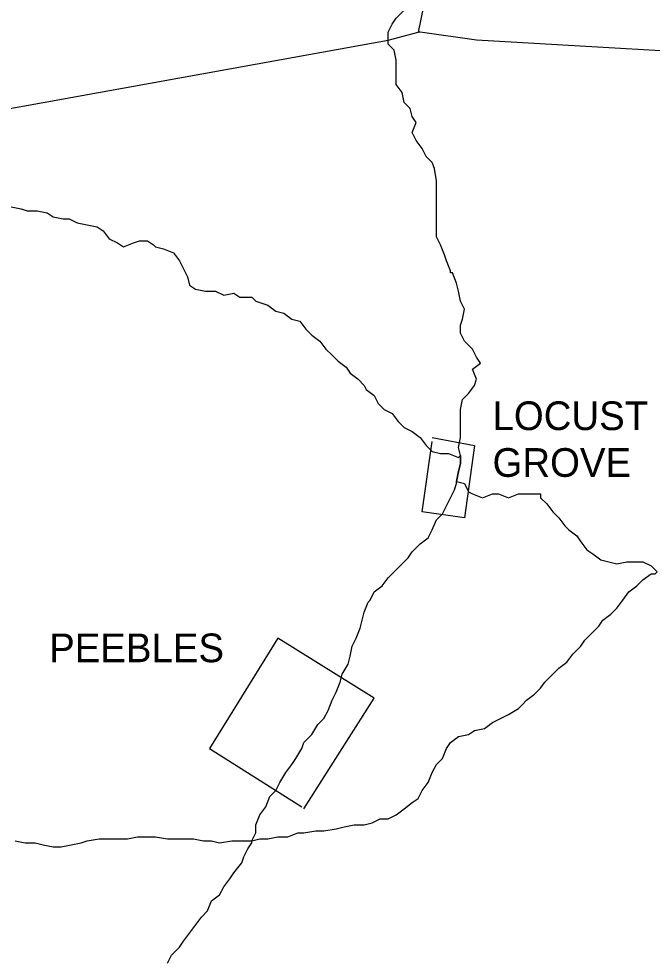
# Model space of a CAD drawing. Extents: x 0 to 34, y 0 to 22.
# Drawn here: x 4.42 to 4.851, y 17.302 to 17.942 of the extents above; entities that cross this region are included whole.
import ezdxf

# ---------------------------------------------------------------- set-up
doc = ezdxf.new("R2010")
doc.units = 0
doc.layers.add('Default', color=7, linetype='Continuous')

msp = doc.modelspace()

# ---------------------------------------------------------------- linework, layer by layer
at = {"layer": 'Default'}
for points in [[(4.8119, 18.57523), (4.78736, 18.44297), (4.76691, 18.32572), (4.75327, 18.24664), (4.73828, 18.1662), (4.72191, 18.0803), (4.69192, 17.93305)], [(4.67147, 17.9276), (4.67147, 17.93305), (4.67419, 17.93851), (4.67692, 17.9426), (4.68238, 17.94805), (4.68647, 17.95351), (4.69192, 17.9576), (4.69192, 17.96305), (4.68919, 17.9685), (4.69192, 17.97396), (4.68783, 17.97941), (4.68783, 17.98623), (4.69056, 17.99168), (4.69192, 17.9985), (4.69192, 18.00668), (4.69192, 18.01077), (4.69192, 18.01077)], [(3.67617, 17.78581), (3.72662, 17.78308), (3.89159, 17.77762), (3.98294, 17.79671), (4.2938, 17.85943), (4.67147, 17.9276), (4.69192, 17.93305)], [(4.94279, 17.91533), (4.73146, 17.9276), (4.69328, 17.93305), (4.69192, 17.93305)], [(4.71373, 17.77081), (4.71101, 17.77762), (4.70964, 17.78171), (4.70692, 17.78853), (4.70419, 17.79399), (4.70419, 17.8008), (4.70419, 17.80762), (4.70419, 17.81444), (4.70419, 17.81989), (4.70419, 17.82671), (4.70419, 17.83216), (4.70283, 17.84034), (4.70146, 17.84443), (4.69737, 17.84852), (4.69465, 17.85398), (4.69056, 17.85943), (4.68783, 17.86488), (4.69056, 17.8717), (4.68783, 17.87579), (4.68647, 17.88124), (4.68238, 17.88533), (4.68101, 17.89215), (4.67692, 17.89761), (4.67692, 17.9017), (4.67692, 17.90851), (4.67692, 17.91397), (4.67556, 17.92078), (4.67147, 17.92487), (4.67147, 17.92624), (4.67147, 17.9276)], [(4.36743, 17.82262), (4.37152, 17.81853), (4.37833, 17.8158), (4.38515, 17.81716), (4.3906, 17.81853), (4.39606, 17.81716), (4.40151, 17.8158), (4.40833, 17.81171), (4.41514, 17.81444), (4.42196, 17.81307), (4.42605, 17.81171), (4.43287, 17.81171), (4.43969, 17.81035), (4.44378, 17.80762), (4.45059, 17.80626), (4.45468, 17.80626)], [(4.45468, 17.80626), (4.46014, 17.80353), (4.46695, 17.80217), (4.47377, 17.8008), (4.47786, 17.79808), (4.48195, 17.79262), (4.48741, 17.7899), (4.4915, 17.78717), (4.49831, 17.7899), (4.5024, 17.79126), (4.50786, 17.79126), (4.51195, 17.78853), (4.51331, 17.78717)], [(4.51331, 17.78717), (4.51876, 17.78581), (4.52558, 17.78308), (4.52967, 17.77762), (4.5324, 17.77217), (4.53513, 17.76672), (4.53649, 17.76126), (4.54058, 17.75854), (4.5474, 17.75717), (4.55421, 17.75717), (4.55967, 17.75445), (4.56648, 17.75581), (4.57057, 17.75308), (4.57194, 17.75308), (4.57194, 17.75308)], [(4.72055, 17.64537), (4.71919, 17.65083), (4.72055, 17.65764), (4.72055, 17.6631), (4.72055, 17.67128), (4.72055, 17.67673), (4.72191, 17.68355), (4.726, 17.68764), (4.7301, 17.69309), (4.73146, 17.69718), (4.72873, 17.704), (4.73419, 17.70809), (4.73146, 17.71218), (4.72873, 17.71763), (4.72328, 17.72309), (4.72055, 17.72854), (4.72055, 17.734), (4.72191, 17.73809), (4.72328, 17.7449), (4.72055, 17.75036), (4.71919, 17.75717), (4.71782, 17.76263), (4.7151, 17.76944), (4.71373, 17.76944), (4.71373, 17.77081)], [(4.57194, 17.75308), (4.57876, 17.75308), (4.58148, 17.75036), (4.58966, 17.74763), (4.59512, 17.74354), (4.60057, 17.74218), (4.60602, 17.73809), (4.61148, 17.73672), (4.61557, 17.73127), (4.61966, 17.72718), (4.62511, 17.72309), (4.6292, 17.71763), (4.63329, 17.71354), (4.63738, 17.70945), (4.64284, 17.70536), (4.64556, 17.70127), (4.65102, 17.69718), (4.65511, 17.69309), (4.65511, 17.69309), (4.65647, 17.69037)], [(4.65647, 17.69037), (4.66192, 17.68628), (4.66465, 17.68082), (4.66874, 17.67673), (4.67419, 17.674), (4.67829, 17.66855), (4.68238, 17.66446), (4.68783, 17.66173), (4.69328, 17.65764), (4.69737, 17.65219), (4.70146, 17.6481), (4.70692, 17.64674), (4.71237, 17.64674), (4.71919, 17.64401), (4.72055, 17.64537)], [(4.70146, 17.65764), (4.7301, 17.65219), (4.72328, 17.60311), (4.69465, 17.6072), (4.70146, 17.65492)], [(4.72055, 17.64537), (4.72055, 17.63992), (4.71919, 17.63447), (4.71782, 17.62765)], [(4.71782, 17.62765), (4.71919, 17.63447), (4.72055, 17.63992), (4.72055, 17.64537)], [(4.6592, 17.54721), (4.66192, 17.55266), (4.66738, 17.55675), (4.67147, 17.5622), (4.67556, 17.56629), (4.67965, 17.57038), (4.6851, 17.57584), (4.68783, 17.57993), (4.69328, 17.58538), (4.69874, 17.58947), (4.70146, 17.59493), (4.70419, 17.60174), (4.70828, 17.60583), (4.71101, 17.61129), (4.71373, 17.61674), (4.71646, 17.62219), (4.71782, 17.62628), (4.71782, 17.62765)], [(4.71782, 17.62765), (4.72328, 17.62628), (4.726, 17.62083), (4.72873, 17.61947), (4.73555, 17.61674), (4.74237, 17.61947), (4.74646, 17.61947), (4.75327, 17.61674), (4.76009, 17.61947), (4.76691, 17.61947), (4.77236, 17.61947), (4.77509, 17.61947), (4.77509, 17.61674)], [(4.77509, 17.61674), (4.77918, 17.61265), (4.78327, 17.6072), (4.78736, 17.60311), (4.79145, 17.59765), (4.79418, 17.59493), (4.79963, 17.59084), (4.80236, 17.58675), (4.80645, 17.58129), (4.81054, 17.57857), (4.81599, 17.57447), (4.82144, 17.57311), (4.8269, 17.57175), (4.83372, 17.57311), (4.84053, 17.57311), (4.84462, 17.57311), (4.85008, 17.57038), (4.85417, 17.56629), (4.85417, 17.56629)], [(4.76554, 17.47904), (4.771, 17.48313), (4.77509, 17.48722), (4.77781, 17.49131), (4.78327, 17.49676), (4.78736, 17.50085), (4.79281, 17.50494), (4.7969, 17.51039), (4.80236, 17.51585), (4.80508, 17.51994), (4.80917, 17.52403), (4.81463, 17.52948), (4.81735, 17.53357), (4.82281, 17.53766), (4.8269, 17.54175), (4.83099, 17.54721), (4.83508, 17.55266), (4.84053, 17.55675), (4.84462, 17.56084), (4.85008, 17.56493), (4.8528, 17.56493), (4.85417, 17.56629)], [(4.6142, 17.4504), (4.61966, 17.45586), (4.62375, 17.46267), (4.62784, 17.46676), (4.63057, 17.47222), (4.63329, 17.47904), (4.63602, 17.48449), (4.63875, 17.49131), (4.64011, 17.49676), (4.6442, 17.50358), (4.64556, 17.50903), (4.64693, 17.51585), (4.64965, 17.5213), (4.65238, 17.52812), (4.65374, 17.53357), (4.65511, 17.53903), (4.65783, 17.54584), (4.6592, 17.54721)], [(4.6142, 17.40541), (4.66192, 17.4804), (4.59648, 17.5213), (4.55012, 17.44631), (4.61284, 17.40677)], [(4.66056, 17.39587), (4.66601, 17.39859), (4.67147, 17.39859), (4.67692, 17.40132), (4.68238, 17.40541), (4.68783, 17.4095), (4.69192, 17.41223), (4.69465, 17.41768), (4.69874, 17.42314), (4.70146, 17.42995), (4.70419, 17.43541), (4.70828, 17.4395), (4.71101, 17.44631), (4.71373, 17.4504), (4.71919, 17.45449), (4.726, 17.45586), (4.7301, 17.45858), (4.73691, 17.45995), (4.74237, 17.46404), (4.74782, 17.46676), (4.75327, 17.46949), (4.76009, 17.47358), (4.76282, 17.47631), (4.76554, 17.47904), (4.76554, 17.47904)], [(4.57876, 17.3836), (4.58148, 17.38905), (4.58148, 17.3945), (4.58421, 17.40132), (4.5883, 17.40677), (4.59103, 17.41359), (4.59512, 17.41768), (4.59784, 17.42314), (4.60193, 17.42995), (4.60602, 17.43541), (4.60875, 17.4395), (4.61284, 17.44631), (4.6142, 17.4504), (4.6142, 17.4504)], [(4.57876, 17.3836), (4.58421, 17.38496), (4.58966, 17.38496), (4.59648, 17.38632), (4.6033, 17.38632), (4.61011, 17.38905), (4.6142, 17.38905), (4.62238, 17.39041), (4.62784, 17.39041), (4.63602, 17.39178), (4.64147, 17.39314), (4.64829, 17.3945), (4.65511, 17.3945), (4.66056, 17.39587)], [(4.41787, 17.3836), (4.42469, 17.38223), (4.43151, 17.38223), (4.43696, 17.38087), (4.44378, 17.37951), (4.44923, 17.37951), (4.45605, 17.38087), (4.46286, 17.38223), (4.46695, 17.3836), (4.47514, 17.38496), (4.48059, 17.38496), (4.48877, 17.38496), (4.49422, 17.38496), (4.50104, 17.38632), (4.50786, 17.38632), (4.51331, 17.38632), (4.52149, 17.38496), (4.52558, 17.38496), (4.5324, 17.38496), (4.53922, 17.38496), (4.54603, 17.3836), (4.55149, 17.3836), (4.55694, 17.38223), (4.56512, 17.3836), (4.57194, 17.3836), (4.57876, 17.3836), (4.57876, 17.3836)], [(4.52149, 17.30043), (4.52422, 17.30588), (4.52967, 17.31133), (4.5324, 17.31542), (4.53649, 17.32088), (4.54058, 17.32633), (4.54467, 17.33179), (4.54876, 17.33588), (4.55149, 17.34269), (4.55694, 17.34678), (4.55967, 17.35224), (4.56376, 17.35769), (4.56648, 17.36178), (4.57194, 17.3686), (4.5733, 17.37269), (4.57603, 17.37814), (4.57876, 17.38223), (4.57876, 17.3836)]]:
    msp.add_lwpolyline(points, dxfattribs=at)

# ---------------------------------------------------------------- texts
for s, p in [('LOCUST', (4.74237, 17.66268)), ('GROVE', (4.74237, 17.63091)), ('PEEBLES', (4.44105, 17.50494))]:
    msp.add_text(s, height=0.019502, dxfattribs=at).set_placement(p)

doc.saveas('drawing.dxf')
